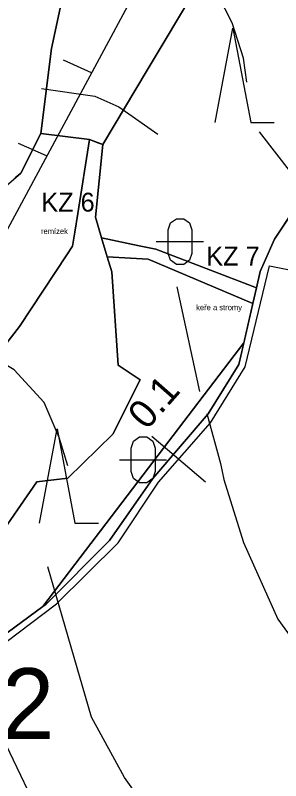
# Model space of a CAD drawing. Extents: x -645676 to -642474, y -1077513 to -1072613.
# Drawn here: x -643612.1 to -643555.9, y -1073757.7 to -1073595.5 of the extents above; entities that cross this region are included whole.
import ezdxf

# ---------------------------------------------------------------- set-up
doc = ezdxf.new("R2010")
doc.units = 0
for name, color, linetype in [('KRAJ_ZELEN_STAV', 7, 'Continuous'), ('Krajinn__zele____popis___stav', 7, 'Continuous'), ('KULTURY_STAV', 7, 'Continuous'), ('KULTURY_ZNACKY', 7, 'Continuous'), ('PC_NAVRH', 7, 'Continuous'), ('PC_OBJ_POPIS_STAV', 7, 'Continuous'), ('PC_STAN_NAVRH', 7, 'Continuous'), ('USES_BK_NAVRH', 7, 'Continuous'), ('VRSTEVNICE', 7, 'Continuous')]:
    doc.layers.add(name, color=color, linetype=linetype)

# ---------------------------------------------------------------- blocks, each defined once
blk = doc.blocks.new('$944')
blk.add_line((0, 1.5), (0, -1.5))
blk = doc.blocks.new('3$0800')
blk.add_lwpolyline([(-0.75, 0), (0, 4), (0.75, 0), (1.75, 0)])
blk = doc.blocks.new('3$1600')
for points in [[(-0.5, 1.5), (-0.4, 1.79), (-0.15, 1.97), (0.16, 1.97), (0.41, 1.79), (0.51, 1.5), (0.51, 0.5), (0.41, 0.21), (0.16, 0.03), (-0.15, 0.03), (-0.4, 0.21), (-0.5, 0.5), (-0.5, 1.5)], [(-1, 1), (0.27, 1), (1, 1)]]:
    blk.add_lwpolyline(points)
blk = doc.blocks.new('2$1030')
blk.add_line((0, 0), (0, -0.5))

msp = doc.modelspace()

# ---------------------------------------------------------------- linework, layer by layer
at = {"layer": 'KRAJ_ZELEN_STAV'}
for points in [[(-643666.67, -1073717.84), (-643662.51, -1073718.35), (-643659.8, -1073721.47), (-643652.06, -1073733.15), (-643639.16, -1073739.94), (-643633.37, -1073729.47), (-643617.8, -1073716.1), (-643616.57, -1073707.38), (-643607.57, -1073694.39), (-643601, -1073693.61), (-643591.43, -1073684.24), (-643585.7, -1073672.75), (-643590.35, -1073669.66), (-643591.69, -1073649.88), (-643595.16, -1073638.25), (-643593.58, -1073622.9), (-643596.38, -1073621.82), (-643606.7, -1073620.55), (-643604.44, -1073602.56), (-643599.28, -1073578.47)], [(-643542.04, -1073620.12), (-643557.26, -1073642.94), (-643560.23, -1073649.8), (-643564.77, -1073669.53), (-643571.29, -1073679.94), (-643583.02, -1073693.68), (-643592.17, -1073706.8), (-643605.56, -1073720.28), (-643618.18, -1073729.53), (-643628.37, -1073737.34), (-643635.32, -1073746.74), (-643651.86, -1073745.19), (-643658.1, -1073733.87), (-643663.24, -1073723.82), (-643666.67, -1073717.84)], [(-643660.99, -1073713.09), (-643652.95, -1073704.65), (-643616.03, -1073649.19), (-643616.72, -1073642.94), (-643624.49, -1073636.93), (-643623.27, -1073632.83), (-643615.66, -1073632.96), (-643610.94, -1073628.93), (-643606.7, -1073620.55), (-643596.38, -1073621.82), (-643599.97, -1073644.41), (-643611.21, -1073661.42), (-643621.25, -1073674.32), (-643641.62, -1073703.8), (-643657.9, -1073714.69), (-643660.99, -1073713.09)]]:
    msp.add_lwpolyline(points, dxfattribs=at)
at = {"layer": 'KULTURY_STAV'}
for points in [[(-643599.28, -1073578.47), (-643604.44, -1073602.56), (-643606.7, -1073620.55), (-643610.94, -1073628.93), (-643612.13, -1073629.94)], [(-643612.13, -1073629.94), (-643610.94, -1073628.93), (-643606.7, -1073620.55), (-643604.44, -1073602.56), (-643599.28, -1073578.47)], [(-643570.22, -1073583.65), (-643541.9, -1073590.02), (-643538.08, -1073592.02), (-643535.19, -1073594.77), (-643535.75, -1073605), (-643542.04, -1073620.12), (-643549.17, -1073630.81), (-643557.26, -1073642.94), (-643559.4, -1073647.88), (-643560.23, -1073649.8), (-643561.02, -1073653.24), (-643582.38, -1073645.07), (-643585.9, -1073644.35), (-643593.85, -1073642.64), (-643595.16, -1073638.25), (-643593.58, -1073622.9), (-643584.17, -1073607.1), (-643573.76, -1073589.62), (-643570.97, -1073584.92), (-643570.76, -1073584.56), (-643570.22, -1073583.65)], [(-643573.76, -1073589.62), (-643584.17, -1073607.1), (-643593.58, -1073622.9), (-643594.61, -1073622.5), (-643596.38, -1073621.82), (-643598.87, -1073637.51), (-643599.5, -1073641.43), (-643599.97, -1073644.41), (-643601.2, -1073646.27), (-643611.21, -1073661.42), (-643621.25, -1073674.32)], [(-643621.25, -1073674.32), (-643611.21, -1073661.42), (-643601.2, -1073646.27), (-643599.97, -1073644.41), (-643599.5, -1073641.43), (-643598.87, -1073637.51), (-643596.38, -1073621.82)], [(-643596.38, -1073621.82), (-643594.61, -1073622.5), (-643593.58, -1073622.9), (-643595.16, -1073638.25), (-643593.85, -1073642.64), (-643592.64, -1073646.72), (-643591.69, -1073649.88), (-643590.35, -1073669.66), (-643585.7, -1073672.75), (-643591.43, -1073684.24), (-643601, -1073693.61), (-643607.57, -1073694.39), (-643616.57, -1073707.38)], [(-643633.51, -1073758.38), (-643633.75, -1073756.87), (-643634.94, -1073749.48), (-643635.32, -1073746.74), (-643628.37, -1073737.34), (-643618.18, -1073729.53), (-643606.29, -1073720.82), (-643605.56, -1073720.28), (-643592.17, -1073706.8), (-643583.02, -1073693.68), (-643571.29, -1073679.94), (-643564.77, -1073669.53), (-643563.72, -1073664.95), (-643561.79, -1073656.58), (-643561.02, -1073653.24), (-643560.23, -1073649.8), (-643559.4, -1073647.88), (-643557.26, -1073642.94), (-643549.17, -1073630.81)], [(-643593.85, -1073642.64), (-643585.9, -1073644.35), (-643582.38, -1073645.07), (-643561.02, -1073653.24), (-643561.79, -1073656.58), (-643583.99, -1073647.18), (-643592.64, -1073646.72), (-643593.85, -1073642.64)], [(-643592.64, -1073646.72), (-643583.99, -1073647.18), (-643561.79, -1073656.58), (-643563.72, -1073664.94), (-643583.9, -1073691.43), (-643606.29, -1073720.82), (-643618.18, -1073729.53), (-643628.37, -1073737.34), (-643635.32, -1073746.74), (-643639.16, -1073739.94), (-643633.37, -1073729.47), (-643617.8, -1073716.1), (-643616.57, -1073707.38), (-643607.57, -1073694.39), (-643601, -1073693.61), (-643591.43, -1073684.24), (-643585.7, -1073672.75), (-643590.35, -1073669.66), (-643591.69, -1073649.88), (-643592.64, -1073646.72)], [(-643563.72, -1073664.94), (-643564.77, -1073669.53), (-643571.29, -1073679.94), (-643583.02, -1073693.68), (-643592.17, -1073706.8), (-643605.56, -1073720.28), (-643606.28, -1073720.81), (-643583.9, -1073691.43), (-643563.72, -1073664.94)]]:
    msp.add_lwpolyline(points, dxfattribs=at)
at = {"layer": 'PC_NAVRH'}
msp.add_lwpolyline([(-643651.3, -1073746.65), (-643642.16, -1073747.03), (-643634.9, -1073748.9), (-643627.26, -1073738.26), (-643603.35, -1073720.23), (-643590.34, -1073707.33), (-643581.82, -1073694.43), (-643570.81, -1073681.9), (-643563.42, -1073670.01), (-643558.29, -1073648.59), (-643471.17, -1073665.87), (-643315.58, -1073698.56), (-643063.81, -1073750.46), (-642778.16, -1073809.87)], dxfattribs=at)
at = {"layer": 'USES_BK_NAVRH'}
msp.add_lwpolyline([(-643507.19, -1073442.54), (-643621.79, -1073655.66), (-643633.31, -1073710.01), (-643602.63, -1073774.11), (-643549.96, -1073850.87), (-643465.95, -1073954.88), (-643402.48, -1074047.21), (-643374.54, -1074085.13), (-643322.34, -1074142.15), (-643301.3, -1074161.69), (-643132.86, -1074291.27), (-643133.86, -1074292.82), (-643146.7, -1074315.23), (-643153.67, -1074324.49), (-643140.05, -1074334.77), (-643371.48, -1074723.77)], dxfattribs=at)
at = {"layer": 'VRSTEVNICE'}
for points in [[(-643563.06, -1073609.67), (-643563.78, -1073604.58), (-643566.2, -1073597.08), (-643572.22, -1073585.3), (-643575.35, -1073581.74), (-643585.32, -1073573.77), (-643591.37, -1073570.42)], [(-643606.57, -1073611.04), (-643595.29, -1073612.65), (-643590.16, -1073614.93), (-643581.92, -1073620.71)], [(-643425.24, -1073751.79), (-643445.46, -1073743.25), (-643462.84, -1073734.85), (-643474.8, -1073728.29), (-643485.34, -1073721.17), (-643488.62, -1073718.04), (-643496.31, -1073712.49), (-643502.43, -1073706.22), (-643509.41, -1073697.25), (-643517.38, -1073685), (-643533.19, -1073655.23), (-643545.3, -1073637.71), (-643553.56, -1073629.03), (-643560.4, -1073620.2)], [(-643577.9, -1073653.06), (-643573.12, -1073675.23)], [(-643601, -1073690.98), (-643602.84, -1073685), (-643605.97, -1073677.59), (-643612.38, -1073670.61), (-643618.93, -1073666.77), (-643631.46, -1073662.5), (-643637.73, -1073661.93), (-643643.2, -1073663)], [(-643571.57, -1073679.89), (-643568.68, -1073690.49), (-643567.95, -1073693.86), (-643563.81, -1073707.22), (-643556.55, -1073723.45), (-643545.01, -1073739.4), (-643534.62, -1073749.8), (-643518.1, -1073760.91), (-643501.58, -1073770.74), (-643478.79, -1073781.99), (-643474.23, -1073785.41), (-643455.15, -1073796.66), (-643435.92, -1073811.33), (-643432.07, -1073815.74), (-643418.97, -1073828.27), (-643389.21, -1073860.46), (-643365.28, -1073881.97)], [(-643369.98, -1073943.49), (-643387.64, -1073931.1), (-643401.88, -1073919.57), (-643411.14, -1073910.74), (-643429.94, -1073890.23), (-643431.93, -1073887.38), (-643432.5, -1073887.52), (-643450.02, -1073868.72), (-643463.83, -1073856.05), (-643467.68, -1073853.63), (-643480.64, -1073843.23), (-643510.12, -1073824.29), (-643535.47, -1073811.04), (-643547.44, -1073802.64), (-643555.7, -1073795.95), (-643566.52, -1073785.83), (-643574.92, -1073776.72), (-643589.02, -1073757.06), (-643596, -1073744.25), (-643605.25, -1073712.36)]]:
    msp.add_lwpolyline(points, dxfattribs=at)

# ---------------------------------------------------------------- block references
at = {"layer": 'KULTURY_ZNACKY', "xscale": 5, "yscale": 5}
for name, p in [('3$0800', (-643566.02, -1073618.22)), ('3$1600', (-643577.25, -1073648.46)), ('3$0800', (-643603.23, -1073703.14)), ('3$1600', (-643585.06, -1073694.7))]:
    msp.add_blockref(name, p, dxfattribs=at)
at = {"layer": 'PC_STAN_NAVRH', "xscale": 5, "yscale": 5.000000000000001, "rotation": 49.516434}
msp.add_blockref('$944', (-643577.51, -1073689.53), dxfattribs=at)
at = {"layer": 'USES_BK_NAVRH', "xscale": 13.000000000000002, "yscale": 12.999999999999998, "rotation": -114.05094800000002}
for p in [(-643595.99, -1073607.68), (-643605.47, -1073625.3)]:
    msp.add_blockref('2$1030', p, dxfattribs=at)

# ---------------------------------------------------------------- texts
at = {"layer": 'Krajinn__zele____popis___stav'}
for s, height, p in [('KZ 6', 4, (-643606.6, -1073637.1)), ('remízek', 1.2, (-643606.67, -1073641.85)), ('KZ 7', 4, (-643571.67, -1073648.53)), ('keře a stromy', 1.2, (-643573.82, -1073658))]:
    msp.add_text(s, height=height, dxfattribs=at).set_placement(p)
at = {"layer": 'PC_OBJ_POPIS_STAV'}
msp.add_text('S12', height=15, dxfattribs=at).set_placement((-643639.54, -1073748.87))
at = {"layer": 'PC_STAN_NAVRH'}
msp.add_text('0.1', height=6, rotation=48.644, dxfattribs=at).set_placement((-643584.28, -1073683.59))

doc.saveas('drawing.dxf')
